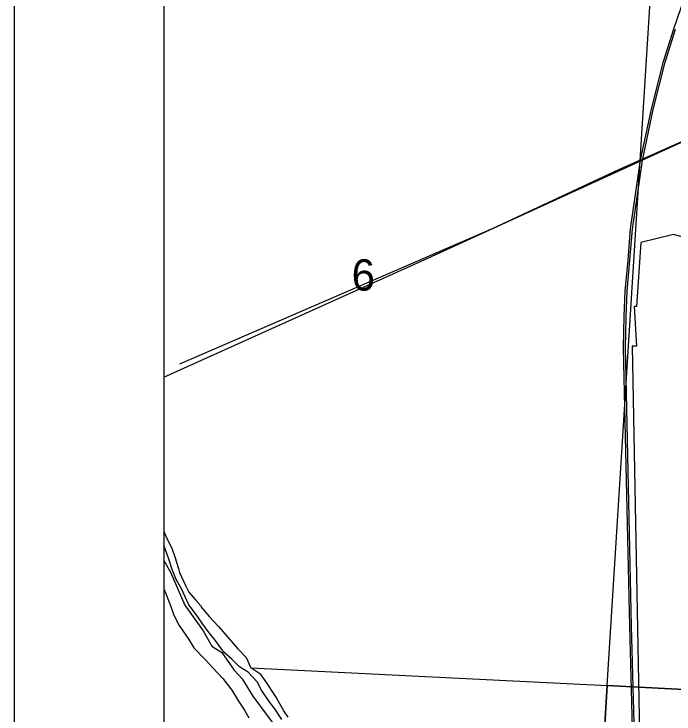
# Model space of a CAD drawing. Extents: x 0 to 42.5, y 0 to 22.
# Drawn here: x 2 to 2.4405, y 19.5152 to 19.9824 of the extents above; entities that cross this region are included whole.
import ezdxf

# ---------------------------------------------------------------- set-up
doc = ezdxf.new("R2010")
doc.units = 0
for name, color, linetype in [('Default', 7, 'Continuous'), ('GM_X_Interchange_Ramps', 7, 'Continuous'), ('GM_X_Major_River', 7, 'Continuous'), ('GM_X_Rail_Line', 7, 'Continuous'), ('GM_X_Section', 7, 'Continuous'), ('GM_X_Section_Text', 7, 'Continuous'), ('GM_X_Unincorporated', 7, 'Continuous'), ('SH_Cut_Line', 7, 'Continuous'), ('SH_Data', 7, 'Continuous')]:
    doc.layers.add(name, color=color, linetype=linetype)

msp = doc.modelspace()

# ---------------------------------------------------------------- linework, layer by layer
at = {"layer": 'Default'}
msp.add_lwpolyline([(2.45491, 19.83113), (2.4401, 19.83517), (2.41843, 19.82994), (2.41555, 19.78707), (2.41398, 19.78715), (2.41548, 19.7607), (2.41264, 19.76072), (2.42127, 19.30123)], dxfattribs=at)
at = {"layer": 'GM_X_Interchange_Ramps'}
msp.add_lwpolyline([(2.1, 20.15481), (2.1, 19.6176), (2.10444, 19.60992), (2.11397, 19.58781), (2.12637, 19.57063), (2.13205, 19.56049), (2.13879, 19.5561), (2.14687, 19.54446), (2.15233, 19.53853), (2.15946, 19.52708), (2.17844, 19.5013)], dxfattribs=at)
at = {"layer": 'GM_X_Major_River'}
for points in [[(2.17877, 19.51141), (2.17408, 19.51866), (2.17032, 19.52344), (2.16525, 19.53107), (2.16225, 19.5366), (2.15641, 19.5431), (2.15056, 19.54675), (2.14548, 19.55172), (2.14001, 19.55651), (2.13418, 19.56434), (2.12967, 19.57026), (2.1261, 19.57523), (2.12159, 19.58153), (2.1167, 19.58802), (2.11427, 19.59336), (2.11165, 19.59907), (2.10828, 19.60499), (2.10567, 19.61166), (2.10362, 19.61775), (2.10175, 19.62289), (2.1, 19.62756)], [(2.1, 19.5986), (2.10159, 19.59496), (2.10476, 19.58696), (2.10662, 19.58124), (2.11018, 19.57419), (2.11619, 19.5656), (2.11994, 19.5593), (2.12748, 19.55184), (2.13256, 19.5463), (2.13933, 19.53884), (2.14535, 19.53101), (2.14986, 19.52376), (2.1538, 19.51765), (2.1568, 19.51269)]]:
    msp.add_lwpolyline(points, dxfattribs=at)
at = {"layer": 'GM_X_Rail_Line'}
for points in [[(2.41536, 19.41214), (2.41099, 19.57381), (2.40738, 19.73951), (2.4069, 19.75963), (2.40738, 19.7804), (2.40802, 19.79751), (2.40994, 19.81811), (2.41157, 19.83894), (2.41828, 19.88478), (2.42542, 19.91896), (2.43358, 19.9507), (2.44046, 19.97259), (2.44764, 19.99334)], [(2.41656, 19.41217), (2.41219, 19.57384), (2.40858, 19.73954), (2.4081, 19.75964), (2.40858, 19.78037), (2.40922, 19.79743), (2.41113, 19.818), (2.41276, 19.83881), (2.41946, 19.88457), (2.42659, 19.91869), (2.43474, 19.95037), (2.44159, 19.97222)], [(2.41935, 19.88483), (2.44256, 19.89543), (2.58445, 19.96001), (2.60953, 19.97146), (2.61481, 19.97387)], [(2.54421, 19.94073), (2.54029, 19.93908), (2.40345, 19.87849), (2.31921, 19.83896), (2.11053, 19.74873)], [(2.1, 19.73996), (2.27616, 19.81948), (2.41935, 19.88483)]]:
    msp.add_lwpolyline(points, dxfattribs=at)
at = {"layer": 'GM_X_Section'}
for points in [[(2.94222, 20.01405), (2.90759, 19.50738), (2.39595, 19.53408), (2.42774, 20.04057)], [(2.39595, 19.53408), (2.90759, 19.50738), (2.87643, 19.01565), (2.83799, 19.01773), (2.36652, 19.04519)]]:
    msp.add_lwpolyline(points, close=True, dxfattribs=at)
msp.add_lwpolyline([(2.18297, 19.51294), (2.18015, 19.51731), (2.17658, 19.52339), (2.17508, 19.52642), (2.16775, 19.53744), (2.16474, 19.54163), (2.15813, 19.54601), (2.39595, 19.53408), (2.36652, 19.04519)], dxfattribs=at)
at = {"layer": 'GM_X_Unincorporated'}
msp.add_lwpolyline([(2.1, 19.9923), (2.1, 19.63718), (2.10135, 19.63379), (2.10548, 19.62524), (2.10735, 19.62012), (2.10977, 19.61234), (2.11052, 19.60969), (2.11464, 19.60039), (2.1167, 19.59659), (2.12104, 19.59146), (2.12443, 19.58765), (2.12537, 19.58613), (2.13026, 19.58024), (2.13648, 19.57358), (2.13949, 19.57016), (2.14948, 19.55874), (2.15494, 19.55285), (2.15813, 19.54601), (2.39595, 19.53408), (2.42774, 20.04057)], dxfattribs=at)
at = {"layer": 'SH_Cut_Line'}
msp.add_lwpolyline([(5.48884, 19.405), (5.50057, 19.55251), (5.51061, 19.66936), (5.5156, 19.73605), (5.52526, 19.85376), (5.53536, 19.98472), (5.54606, 20.11658), (5.56474, 20.34561), (5.56563, 20.35496), (5.56586, 20.35729), (5.60252, 20.8068), (5.60957, 20.9), (2.1, 20.9), (2.1, 16.00757)], dxfattribs=at)
at = {"layer": 'SH_Data'}
for p, q in [((2, 21), (2, 14)), ((2.1, 20.9), (2.1, 14.1))]:
    msp.add_line(p, q, dxfattribs=at)

# ---------------------------------------------------------------- texts
at = {"layer": 'GM_X_Section_Text'}
msp.add_text('6', height=0.02093, rotation=0, dxfattribs=at).set_placement((2.22537, 19.79777))

doc.saveas('drawing.dxf')
